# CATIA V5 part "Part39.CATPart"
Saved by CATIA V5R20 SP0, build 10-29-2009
Part number: 9FA 042212
Revision: ANY
Definition: UNKNOWN
Nomenclature: 9FA 042212
Source: Unknown
Bounding box of the stored display mesh (mm): x -10 to 10, y 0.13 to 20.13, z -10 to 10
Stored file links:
  C:\Users\Utente\Desktop\IO LAVORO\3D X SITO CF\CUMSA\3D files FA\FA 2007SF\Part39.CATPart

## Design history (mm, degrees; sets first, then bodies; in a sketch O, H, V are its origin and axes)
Body1 "Cortar-Extruir4" (main body)
  Solid1: solid without history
